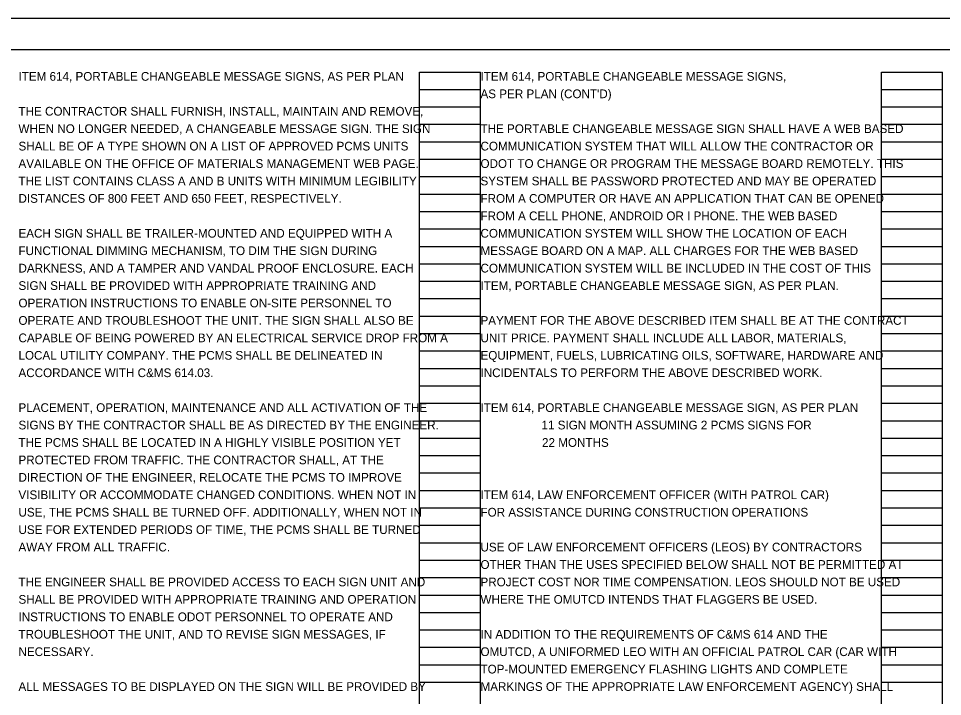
# Model space of a CAD drawing. Extents: x -18.5 to 46, y -14.2 to 42.5.
# Drawn here: x 9.82 to 24.66, y 11.11 to 22 of the extents above; entities that cross this region are included whole.
import ezdxf

# ---------------------------------------------------------------- set-up
doc = ezdxf.new("R2010")
doc.units = 0
for name, color, linetype in [('SH_Border', 7, 'Continuous'), ('SH_Cut_Line', 7, 'Continuous'), ('SH_Data', 7, 'Continuous'), ('SH_Text', 7, 'Continuous')]:
    doc.layers.add(name, color=color, linetype=linetype)

msp = doc.modelspace()

# ---------------------------------------------------------------- linework, layer by layer
at = {"layer": 'SH_Border'}
msp.add_lwpolyline([(1.5, 21.5), (33.5, 21.5), (33.5, 0.5), (1.5, 0.5)], close=True, dxfattribs=at)
at = {"layer": 'SH_Cut_Line'}
msp.add_lwpolyline([(0, 0), (34, 0), (34, 22), (0, 22)], close=True, dxfattribs=at)
at = {"layer": 'SH_Data'}
for p, q in [((16.26, 0.98), (16.26, 21.14)), ((16.26, 21.14), (17.24, 21.14)), ((17.24, 0.98), (17.24, 21.14)), ((23.68, 0.98), (23.68, 21.14)), ((23.68, 21.14), (24.66, 21.14)), ((24.66, 0.98), (24.66, 21.14)), ((16.26, 20.86), (17.24, 20.86)), ((23.68, 20.86), (24.66, 20.86)), ((16.26, 20.58), (17.24, 20.58)), ((23.68, 20.58), (24.66, 20.58)), ((16.26, 20.3), (17.24, 20.3)), ((23.68, 20.3), (24.66, 20.3)), ((16.26, 20.02), (17.24, 20.02)), ((23.68, 20.02), (24.66, 20.02)), ((16.26, 19.74), (17.24, 19.74)), ((23.68, 19.74), (24.66, 19.74)), ((16.26, 19.46), (17.24, 19.46)), ((23.68, 19.46), (24.66, 19.46)), ((16.26, 19.18), (17.24, 19.18)), ((23.68, 19.18), (24.66, 19.18)), ((16.26, 18.9), (17.24, 18.9)), ((23.68, 18.9), (24.66, 18.9)), ((16.26, 18.62), (17.24, 18.62)), ((23.68, 18.62), (24.66, 18.62)), ((16.26, 18.34), (17.24, 18.34)), ((23.68, 18.34), (24.66, 18.34)), ((16.26, 18.06), (17.24, 18.06)), ((23.68, 18.06), (24.66, 18.06)), ((16.26, 17.78), (17.24, 17.78)), ((23.68, 17.78), (24.66, 17.78)), ((16.26, 17.5), (17.24, 17.5)), ((23.68, 17.5), (24.66, 17.5)), ((16.26, 17.22), (17.24, 17.22)), ((23.68, 17.22), (24.66, 17.22)), ((16.26, 16.94), (17.24, 16.94)), ((23.68, 16.94), (24.66, 16.94)), ((16.26, 16.66), (17.24, 16.66)), ((23.68, 16.66), (24.66, 16.66)), ((16.26, 16.38), (17.24, 16.38)), ((23.68, 16.38), (24.66, 16.38)), ((16.26, 16.1), (17.24, 16.1)), ((23.68, 16.1), (24.66, 16.1)), ((16.26, 15.82), (17.24, 15.82)), ((23.68, 15.82), (24.66, 15.82)), ((16.26, 15.54), (17.24, 15.54)), ((23.68, 15.54), (24.66, 15.54)), ((16.26, 15.26), (17.24, 15.26)), ((23.68, 15.26), (24.66, 15.26)), ((16.26, 14.98), (17.24, 14.98)), ((23.68, 14.98), (24.66, 14.98)), ((16.26, 14.7), (17.24, 14.7)), ((23.68, 14.7), (24.66, 14.7)), ((16.26, 14.42), (17.24, 14.42)), ((23.68, 14.42), (24.66, 14.42)), ((16.26, 14.14), (17.24, 14.14)), ((23.68, 14.14), (24.66, 14.14)), ((16.26, 13.86), (17.24, 13.86)), ((23.68, 13.86), (24.66, 13.86)), ((16.26, 13.58), (17.24, 13.58)), ((23.68, 13.58), (24.66, 13.58)), ((16.26, 13.3), (17.24, 13.3)), ((23.68, 13.3), (24.66, 13.3)), ((16.26, 13.02), (17.24, 13.02)), ((23.68, 13.02), (24.66, 13.02)), ((16.26, 12.74), (17.24, 12.74)), ((23.68, 12.74), (24.66, 12.74)), ((16.26, 12.46), (17.24, 12.46)), ((23.68, 12.46), (24.66, 12.46)), ((16.26, 12.18), (17.24, 12.18)), ((23.68, 12.18), (24.66, 12.18)), ((16.26, 11.9), (17.24, 11.9)), ((23.68, 11.9), (24.66, 11.9)), ((16.26, 11.62), (17.24, 11.62)), ((23.68, 11.62), (24.66, 11.62)), ((16.26, 11.34), (17.24, 11.34)), ((23.68, 11.34), (24.66, 11.34))]:
    msp.add_line(p, q, dxfattribs=at)

# ---------------------------------------------------------------- texts
at = {"layer": 'SH_Text'}
for s, p in [('ITEM 614, PORTABLE CHANGEABLE MESSAGE SIGNS, AS PER PLAN', (9.82, 21)), ('ITEM 614, PORTABLE CHANGEABLE MESSAGE SIGNS, ', (17.24, 21)), ("AS PER PLAN (CONT'D)", (17.24, 20.72)), ('THE CONTRACTOR SHALL FURNISH, INSTALL, MAINTAIN AND REMOVE, ', (9.82, 20.44)), ('WHEN NO LONGER NEEDED, A CHANGEABLE MESSAGE SIGN. THE SIGN ', (9.82, 20.16)), ('THE PORTABLE CHANGEABLE MESSAGE SIGN SHALL HAVE A WEB BASED ', (17.24, 20.16)), ('SHALL BE OF A TYPE SHOWN ON A LIST OF APPROVED PCMS UNITS ', (9.82, 19.88)), ('COMMUNICATION SYSTEM THAT WILL ALLOW THE CONTRACTOR OR ', (17.24, 19.88)), ('AVAILABLE ON THE OFFICE OF MATERIALS MANAGEMENT WEB PAGE. ', (9.82, 19.6)), ('ODOT TO CHANGE OR PROGRAM THE MESSAGE BOARD REMOTELY. THIS ', (17.24, 19.6)), ('THE LIST CONTAINS CLASS A AND B UNITS WITH MINIMUM LEGIBILITY ', (9.82, 19.32)), ('SYSTEM SHALL BE PASSWORD PROTECTED AND MAY BE OPERATED ', (17.24, 19.32)), ('DISTANCES OF 800 FEET AND 650 FEET, RESPECTIVELY.', (9.82, 19.04)), ('FROM A COMPUTER OR HAVE AN APPLICATION THAT CAN BE OPENED ', (17.24, 19.04)), ('FROM A CELL PHONE, ANDROID OR I PHONE. THE WEB BASED ', (17.24, 18.76)), ('EACH SIGN SHALL BE TRAILER-MOUNTED AND EQUIPPED WITH A ', (9.82, 18.48)), ('COMMUNICATION SYSTEM WILL SHOW THE LOCATION OF EACH ', (17.24, 18.48)), ('FUNCTIONAL DIMMING MECHANISM, TO DIM THE SIGN DURING', (9.82, 18.2)), ('MESSAGE BOARD ON A MAP. ALL CHARGES FOR THE WEB BASED ', (17.24, 18.2)), ('DARKNESS, AND A TAMPER AND VANDAL PROOF ENCLOSURE. EACH ', (9.82, 17.92)), ('COMMUNICATION SYSTEM WILL BE INCLUDED IN THE COST OF THIS ', (17.24, 17.92)), ('SIGN SHALL BE PROVIDED WITH APPROPRIATE TRAINING AND ', (9.82, 17.64)), ('ITEM, PORTABLE CHANGEABLE MESSAGE SIGN, AS PER PLAN. ', (17.24, 17.64)), ('OPERATION INSTRUCTIONS TO ENABLE ON-SITE PERSONNEL TO ', (9.82, 17.36)), ('OPERATE AND TROUBLESHOOT THE UNIT. THE SIGN SHALL ALSO BE ', (9.82, 17.08)), ('PAYMENT FOR THE ABOVE DESCRIBED ITEM SHALL BE AT THE CONTRACT ', (17.24, 17.08)), ('CAPABLE OF BEING POWERED BY AN ELECTRICAL SERVICE DROP FROM A ', (9.82, 16.8)), ('UNIT PRICE. PAYMENT SHALL INCLUDE ALL LABOR, MATERIALS, ', (17.24, 16.8)), ('LOCAL UTILITY COMPANY. THE PCMS SHALL BE DELINEATED IN ', (9.82, 16.52)), ('EQUIPMENT, FUELS, LUBRICATING OILS, SOFTWARE, HARDWARE AND ', (17.24, 16.52)), ('ACCORDANCE WITH C&MS 614.03.', (9.82, 16.24)), ('INCIDENTALS TO PERFORM THE ABOVE DESCRIBED WORK.', (17.24, 16.24)), ('PLACEMENT, OPERATION, MAINTENANCE AND ALL ACTIVATION OF THE ', (9.82, 15.68)), ('ITEM 614, PORTABLE CHANGEABLE MESSAGE SIGN, AS PER PLAN ', (17.24, 15.68)), ('SIGNS BY THE CONTRACTOR SHALL BE AS DIRECTED BY THE ENGINEER. ', (9.82, 15.4)), ('11 SIGN MONTH ASSUMING 2 PCMS SIGNS FOR ', (18.22, 15.4)), ('THE PCMS SHALL BE LOCATED IN A HIGHLY VISIBLE POSITION YET ', (9.82, 15.12)), ('                   22 MONTHS', (17.24, 15.12)), ('PROTECTED FROM TRAFFIC. THE CONTRACTOR SHALL, AT THE ', (9.82, 14.84)), ('DIRECTION OF THE ENGINEER, RELOCATE THE PCMS TO IMPROVE ', (9.82, 14.56)), ('VISIBILITY OR ACCOMMODATE CHANGED CONDITIONS. WHEN NOT IN ', (9.82, 14.28)), ('ITEM 614, LAW ENFORCEMENT OFFICER (WITH PATROL CAR)', (17.24, 14.28)), ('USE, THE PCMS SHALL BE TURNED OFF. ADDITIONALLY, WHEN NOT IN ', (9.82, 14)), ('FOR ASSISTANCE DURING CONSTRUCTION OPERATIONS', (17.24, 14)), ('USE FOR EXTENDED PERIODS OF TIME, THE PCMS SHALL BE TURNED ', (9.82, 13.72)), ('AWAY FROM ALL TRAFFIC.', (9.82, 13.44)), ('USE OF LAW ENFORCEMENT OFFICERS (LEOS) BY CONTRACTORS', (17.24, 13.44)), ('OTHER THAN THE USES SPECIFIED BELOW SHALL NOT BE PERMITTED AT ', (17.24, 13.16)), ('THE ENGINEER SHALL BE PROVIDED ACCESS TO EACH SIGN UNIT AND ', (9.82, 12.88)), ('PROJECT COST NOR TIME COMPENSATION. LEOS SHOULD NOT BE USED ', (17.24, 12.88)), ('SHALL BE PROVIDED WITH APPROPRIATE TRAINING AND OPERATION ', (9.82, 12.6)), ('WHERE THE OMUTCD INTENDS THAT FLAGGERS BE USED.', (17.24, 12.6)), ('INSTRUCTIONS TO ENABLE ODOT PERSONNEL TO OPERATE AND ', (9.82, 12.32)), ('TROUBLESHOOT THE UNIT, AND TO REVISE SIGN MESSAGES, IF ', (9.82, 12.04)), ('IN ADDITION TO THE REQUIREMENTS OF C&MS 614 AND THE', (17.24, 12.04)), ('NECESSARY.', (9.82, 11.76)), ('OMUTCD, A UNIFORMED LEO WITH AN OFFICIAL PATROL CAR (CAR WITH ', (17.24, 11.76)), ('TOP-MOUNTED EMERGENCY FLASHING LIGHTS AND COMPLETE ', (17.24, 11.48)), ('ALL MESSAGES TO BE DISPLAYED ON THE SIGN WILL BE PROVIDED BY ', (9.82, 11.2)), ('MARKINGS OF THE APPROPRIATE LAW ENFORCEMENT AGENCY) SHALL ', (17.24, 11.2))]:
    msp.add_text(s, height=0.14, dxfattribs=at).set_placement(p)

doc.saveas('drawing.dxf')
